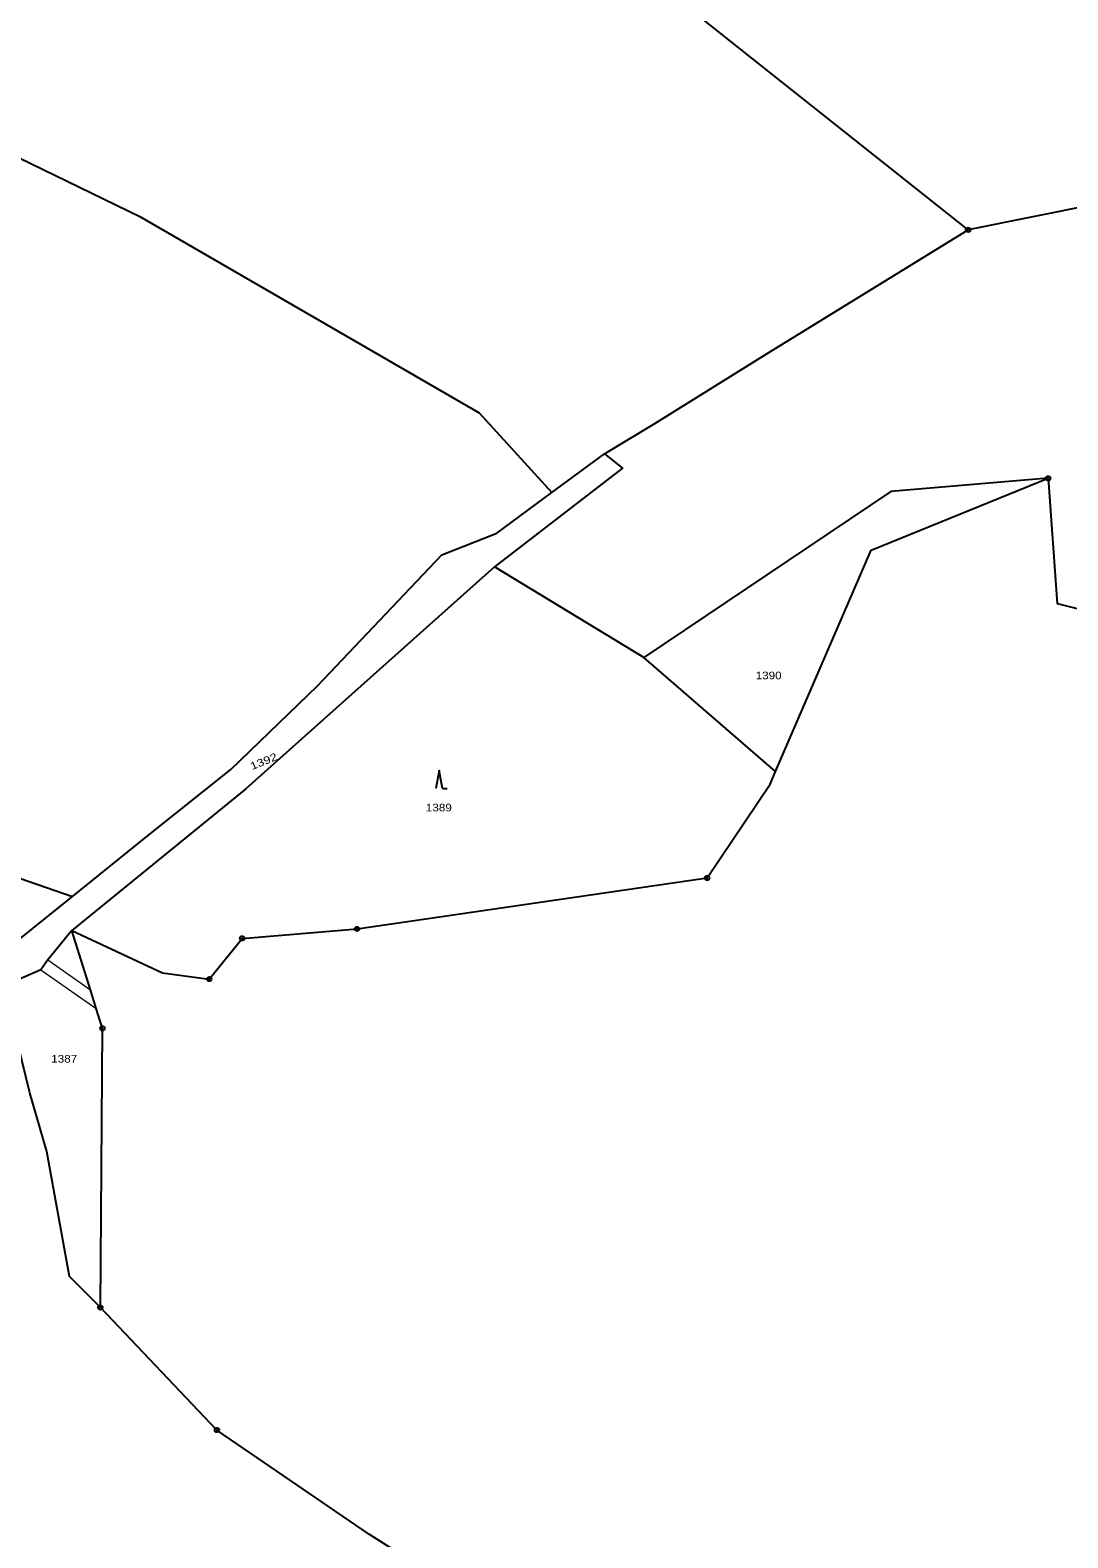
# Model space of a CAD drawing. Extents: x -872229 to -869198, y -1075981 to -1074329.
# Drawn here: x -870272.3 to -870040, y -1074936.4 to -1074598.7 of the extents above; entities that cross this region are included whole.
import ezdxf

# ---------------------------------------------------------------- set-up
doc = ezdxf.new("R2010")
doc.units = 0
doc.header["$LTSCALE"] = 0.68
for name, color, linetype, lineweight in [('1', 7, 'Continuous', 25), ('3', 7, 'Continuous', 25), ('4', 7, 'Continuous', 13), ('8', 7, 'Continuous', 25)]:
    doc.layers.add(name, color=color, linetype=linetype, lineweight=lineweight)
doc.layers.add('2', color=7, linetype='Continuous')

msp = doc.modelspace()

# ---------------------------------------------------------------- linework, layer by layer
at = {"layer": '1'}
msp.add_line((-870274.68, -1074802.33), (-870262.81, -1074792.73), dxfattribs=at)
for points in [[(-870143.77, -1074693.61), (-870132.5, -1074686.79), (-870106.37, -1074670.55), (-870062.32, -1074643.41), (-870191.72, -1074540.63)], [(-870357.04, -1074569.54), (-870334.99, -1074573.21), (-870317.65, -1074591.75), (-870314.76, -1074611.74), (-870277.71, -1074625.88), (-870247.77, -1074640.47), (-870171.77, -1074684.38), (-870155.5, -1074702.23), (-870143.77, -1074693.61)], [(-869844.44, -1074604.77), (-869905.34, -1074611.83), (-870062.32, -1074643.41)], [(-870044.43, -1074699.07), (-870042.4, -1074727.1), (-870020.9, -1074732.51), (-870004.05, -1074723.11), (-869911.02, -1074678.28)], [(-870143.77, -1074693.61), (-870139.73, -1074696.8), (-870168.33, -1074718.91)], [(-870262.81, -1074792.73), (-870246.17, -1074779.27), (-870227.38, -1074764.31), (-870207.96, -1074745.59), (-870180.13, -1074716.24), (-870167.86, -1074711.4), (-870155.5, -1074702.23)], [(-870044.43, -1074699.07), (-870079.61, -1074702.06), (-870134.93, -1074739.24)], [(-870105.49, -1074764.74), (-870084.01, -1074715.16), (-870044.43, -1074699.07)], [(-870168.33, -1074718.91), (-870224.05, -1074768.66), (-870263, -1074800.37)], [(-870263, -1074800.37), (-870242.65, -1074809.81), (-870232.21, -1074811.24), (-870224.84, -1074802.12), (-870199.14, -1074800), (-870120.77, -1074788.59), (-870106.68, -1074767.61), (-870105.49, -1074764.74), (-870134.93, -1074739.24), (-870168.33, -1074718.91)], [(-870383.96, -1074724.98), (-870370.29, -1074739.68), (-870354.63, -1074752.92), (-870327.13, -1074770.46), (-870262.81, -1074792.73)], [(-870263, -1074800.37), (-870268.38, -1074806.91), (-870269.92, -1074809.15), (-870277.75, -1074812.62), (-870281.03, -1074819.44)], [(-870256.59, -1074884.78), (-870256.11, -1074822.27), (-870257.5, -1074817.83), (-870258.82, -1074813.64), (-870263, -1074800.37)], [(-870256.59, -1074884.78), (-870263.53, -1074877.85), (-870268.59, -1074849.87), (-870272.4, -1074836.68), (-870275.99, -1074822.05), (-870281.03, -1074819.44)], [(-870115.36, -1074981.96), (-870158.79, -1074959.47), (-870196.33, -1074935.63), (-870230.5, -1074912.24), (-870256.59, -1074884.78)]]:
    msp.add_lwpolyline(points, dxfattribs=at)
at = {"layer": '3'}
msp.add_line((-870179.97, -1074768.54), (-870178.974, -1074768.54), dxfattribs=at)
msp.add_lwpolyline([(-870179.97, -1074768.54), (-870180.72, -1074764.54), (-870181.47, -1074768.54)], dxfattribs=at)
at = {"layer": '4'}
for p, q in [((-870268.38, -1074806.91), (-870258.82, -1074813.64)), ((-870269.92, -1074809.15), (-870257.5, -1074817.83))]:
    msp.add_line(p, q, dxfattribs=at)
at = {"layer": '8'}
for centre, radius in [((-870062.32, -1074643.4099), 0.5), ((-870062.32, -1074643.4099), 0.0303), ((-870044.43, -1074699.0699), 0.5), ((-870044.43, -1074699.0699), 0.0303), ((-870120.77, -1074788.5899), 0.5), ((-870120.77, -1074788.5899), 0.0303), ((-870199.14, -1074799.9999), 0.5), ((-870199.14, -1074799.9999), 0.0303), ((-870224.84, -1074802.1199), 0.5), ((-870224.84, -1074802.1199), 0.0303), ((-870232.21, -1074811.2399), 0.5), ((-870232.21, -1074811.2399), 0.0303), ((-870256.11, -1074822.2699), 0.5), ((-870256.11, -1074822.2699), 0.0303), ((-870256.59, -1074884.7799), 0.5), ((-870256.59, -1074884.7799), 0.0303), ((-870230.5, -1074912.2399), 0.5), ((-870230.5, -1074912.2399), 0.0303)]:
    msp.add_circle(centre, radius, dxfattribs=at)

# ---------------------------------------------------------------- texts
at = {"layer": '2', "width": 1.15}
for s, p in [('1390', (-870109.91, -1074744.08)), ('1389', (-870183.73, -1074773.67)), ('1387', (-870267.59, -1074829.94))]:
    msp.add_text(s, height=1.7, dxfattribs=at).set_placement(p)
at = {"layer": '2', "width": 1.25}
msp.add_text('1392', height=1.7, rotation=22, dxfattribs=at).set_placement((-870222.631, -1074764.438))

doc.saveas('drawing.dxf')
